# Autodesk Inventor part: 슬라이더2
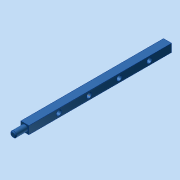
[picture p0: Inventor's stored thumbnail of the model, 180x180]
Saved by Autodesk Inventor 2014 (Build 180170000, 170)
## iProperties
Company: 한국ATC센터
Created: 2015-04
Part Number: 슬라이더2
Document SubType Name: Modeling
Designer: KYOUNG IL JANG
Density: 1 g/cm^3
Material: 일반
Mass: 8.7906 g
Surface Area: 52.3143 cm^2
Volume: 8.7906 cm^3
Appearance: 하늘색 짙음
Author: KYOUNG IL JANG
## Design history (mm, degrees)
sketch "스케치3"
  geometry: L1 (4, 142)-(-4, 142); L2 (-4, 142)-(-4, 0); L3 (-4, 0)-(4, 0); L4 (4, 0)-(4, 142); 3 further points
  constraints: 8 end point, 2 coincident, 2 parallel, 1 horizontal, 1 midpoint, 1 perpendicular
  dimensions: "d5" = 8 distance of L1.start L1.end; "d6" = 142 distance of L1.end L2.end
extrude "돌출3" new body sketch "스케치3" stored distance "d7" = 8; taper "d8" = 0 deg
sketch "스케치4"
  geometry: L1 (8, 0)-(0, 0) reference; 3 further points
  constraints: 1 midpoint, 1 vertical alignment
  dimensions: "d9" = 30 distance of point (4, 30) point (4, 0)
hole "구멍1" sketch "스케치4" at (4, 30) diameter "d10" = 5; stored, may be unused: countersink angle "d14" = 90 deg, drill point angle "d16" = 118 deg; dims "d11" = 6, "d12" = 4, "d13" = 2, "d15" = 8
sketch "스케치5"
  geometry: C1 r 3 at (4, -4); 1 further point
  constraints: 1 centre point, 1 coincident
  dimensions: "d20" = 6 diameter of C1
extrude "돌출4" join sketch "스케치5" distance "d21" = 12; taper "d22" = 0 deg
chamfer "모따기1" distance "d23" = 1; stored, may be unused: second distance "d24" = 2, angle "d25" = 45 deg
node "작업 평면2"
  node "작업축1"
node "솔리드1"
pattern_linear "직사각형 패턴1" dims "d19" = 30
node "솔리드2"
other parameters: "d26" = 0
